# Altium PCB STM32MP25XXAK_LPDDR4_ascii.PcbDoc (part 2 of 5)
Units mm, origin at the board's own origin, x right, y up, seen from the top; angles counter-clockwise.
Board outline 120 x 79.6 mm, 4 copper layers (Top Layer, Signal Layer 1, Signal Layer 2, Bottom Layer), stack 1.614 mm thick; 190 components, 143 nets, 1208 pads, 757 vias.
Unrouted connection lines stored in the file: 3.
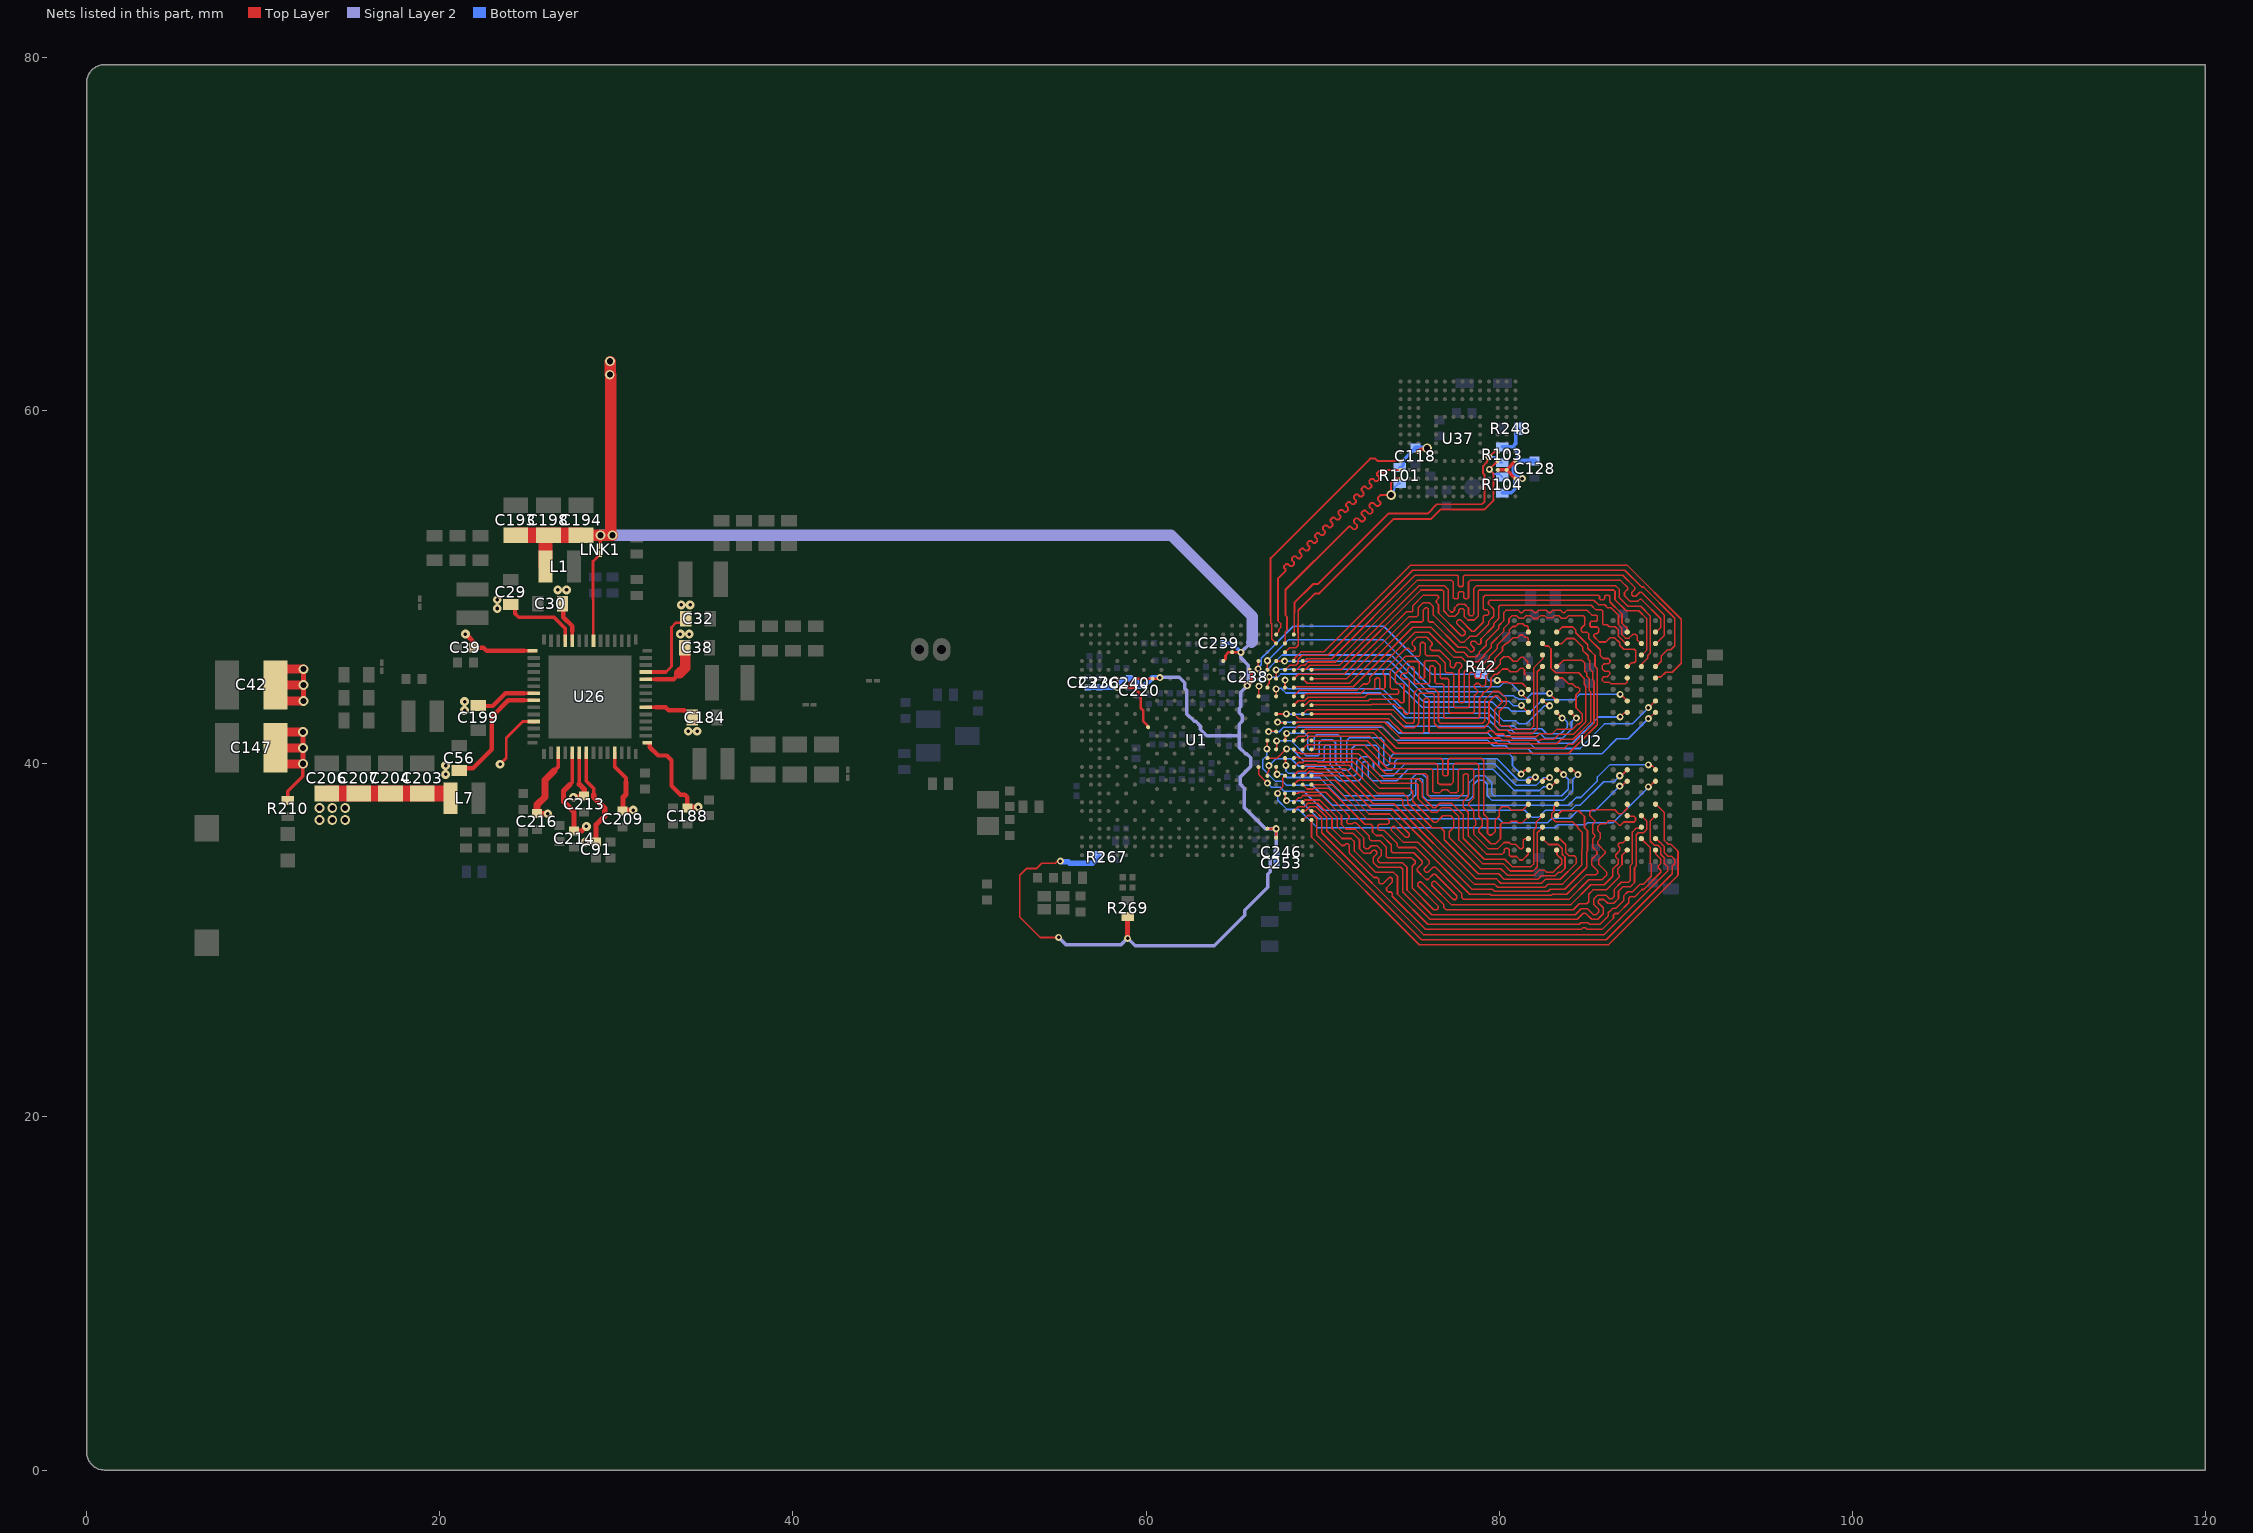
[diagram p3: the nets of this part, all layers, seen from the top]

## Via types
v1: diameter 0.55, hole 0.35, Top Layer to Bottom Layer, 277 vias
v2: diameter 0.4, hole 0.2, Top Layer to Bottom Layer, tented both sides, 229 vias
v3: diameter 0.5, hole 0.2, Top Layer to Bottom Layer, 146 vias
v4: diameter 0.4, hole 0.2, Top Layer to Bottom Layer, 105 vias

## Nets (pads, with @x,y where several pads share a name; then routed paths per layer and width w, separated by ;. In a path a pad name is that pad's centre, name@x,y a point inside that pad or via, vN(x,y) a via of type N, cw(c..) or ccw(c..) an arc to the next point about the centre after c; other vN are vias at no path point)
1V8: C118.2 C128.2 C193.2 C194.2 C198.2 C220.2 C236.2 C237.2 C238.2 C239.2 C240.2 C246.2 C253.2 L1.2 LNK1.2 R101.2 R103.2 R104.2 R248.2 R267.2 R269.1 U1.1E1 U1.AD22 U1.AE23 U1.D18 U1.E17 U1.F20 U1.G5 U1.G7 U1.G9 U1.G19 U1.H6 U37.C6 U37.M4 U37.N4 U37.P3 U37.P5 | length 137.4
  Top Layer w0.1: v2(55.049,30.165) 54.012,30.165 52.854,31.323 52.854,33.688 53.244,34.078 53.813,34.078 54.103,34.368 54.86,34.368 54.967,34.474 55.127,34.474 v2(55.146,34.494)
  Top Layer w0.15: U1.G5@58.375,44.825 v2(58.375,44.325) U1.H6@58.875,44.325 ; U1.1E1@60.125,42.075 60.125,42.097 60.085,42.137 60.085,42.17 59.835,42.42 59.835,43.035 59.702,43.168 59.702,43.926 59.304,44.325 U1.H6@58.875,44.325 ; v2@60.792,44.887 v2(60.79,44.885) 60.73,44.825 U1.G9@60.375,44.825 U1.G7@59.375,44.825 U1.H6@58.875,44.325 ; U1.E17@64.375,45.825 64.375,45.828 64.5,45.953 64.5,46.139 64.683,46.322 U1.D18@64.872,46.322 ; U1.D18@64.853,46.325 U1.D18@64.875,46.325 65.372,46.325 v2(65.378,46.319) ; U1.G19@65.378,44.822 65.735,44.465 v2(65.735,44.426) 65.735,44.412 65.973,44.651 65.973,45.205 65.875,45.303 U1.F20@65.875,45.325 ; U1.AD22@66.875,36.325 v2(67.375,36.325) U1.AE23@67.375,35.825 ; U37.P3@80.925,56.155 v2(81.325,56.155)
  Top Layer w0.2: LNK1.2@29.1,52.348 v1(29.1,52.95) ; U37.C6@75.425,57.655 75.602,57.832 75.877,57.832 v1(75.925,57.88) ; U37.M4@79.925,56.655 U37.N4@80.425,56.655 ; U37.P3@80.925,56.155 U37.N4@80.425,56.655 ; U37.P5@80.925,57.155 U37.N4@80.425,56.655
  Top Layer w0.3: R269.1@58.956,31.358 58.956,30.117 v2(58.962,30.112)
  Top Layer w0.64: C194.2@28,52.95 v1(29.1,52.95) v1(29.78,52.95) 29.674,53.056 v1@29.674,62.004 ; v1@29.66,62.075 v1@29.66,62.782
  Top Layer w0.8: L1.2@25.995,51.175 25.995,52.9 26.045,52.95 C198.2@26.15,52.95
  Top Layer w0.9: C193.2@24.3,52.95 C198.2@26.045,52.95 ; C198.2@26.15,52.95 C194.2@28,52.95
  Signal Layer 2 w0.2: v2(55.049,30.165) 55.449,29.766 58.598,29.766 v2@58.944,30.112 ; v2(58.962,30.112) 59.386,29.688 63.861,29.688 65.603,31.43 65.603,31.711 66.9,33.008 66.9,33.754 67.041,33.895 67.041,34.559 67.375,34.893 v2(67.375,36.325) ; v2(60.79,44.885) 60.811,44.906 61.89,44.906 62.2,44.596 62.2,44.264 62.32,44.144 62.32,42.814 62.725,42.409 62.81,42.409 63.077,42.143 ; 63.075,42.156 63.077,42.155 63.077,42.143 ; 65.285,41.575 65.285,40.928 65.64,40.572 65.694,40.572 65.93,40.336 65.93,39.851 65.349,39.271 65.349,38.835 65.569,38.615 65.569,37.527 65.566,37.525 66.77,36.322 v2@67.372,36.322 ; v2@65.674,44.353 65.773,44.452 65.773,44.591 65.794,44.612 65.794,45.583 65.378,45.999 v2(65.378,46.319) 65.927,46.868 65.981,46.868 ; v2@65.734,44.411 65.375,44.053 65.375,43.231 65.284,43.14 65.284,42.894 65.44,42.738 65.44,42.406 65.285,42.251 65.285,41.593 63.445,41.593 63.077,41.961 63.077,42.143
  Signal Layer 2 w0.64: v1@29.1,52.955 v1@29.78,52.955 ; v1(29.78,52.95) 61.405,52.95 ; 61.411,52.956 66.023,48.344 66.023,46.91 65.981,46.868
  Bottom Layer w0.15: v2(67.375,36.325) 67.375,34.827 67.391,34.811
  Bottom Layer w0.2: C239.2@64.4,46.837 64.86,46.837 v2(65.378,46.319) ; v2@65.735,44.411 65.958,44.635 65.958,44.819 C238.2@66.033,44.894 ; R101.2@74.375,56.775 74.425,56.775 74.58,56.93 74.58,57.2 75.08,57.7 75.08,57.725 75.235,57.88 C118.2@75.26,57.88 ; R103.2@80.171,57.961 80.769,57.961 ; R104.2@80.175,55.355 80.69,55.355 80.885,55.55 80.885,55.998 81.061,56.174 ; 81.075,57.136 81.075,57.655 80.769,57.961 ; R248.2@81.107,58.98 80.952,58.825 80.952,58.144 80.769,57.961
  Bottom Layer w0.25: C253.2@67.391,34.385 67.391,34.811 C246.2@67.391,34.986
  Bottom Layer w0.3: v2(55.146,34.494) 55.165,34.474 55.236,34.474 55.259,34.452 55.612,34.452 55.689,34.375 56.975,34.375 57.123,34.523 57.218,34.523 57.323,34.628 R267.2@57.323,34.723 ; C237.2@56.696,44.325 C236.2@57.35,44.325 v2@58.386,44.325 ; v2(58.375,44.325) 58.394,44.344 58.394,44.53 58.689,44.825 59.025,44.825 C240.2@59.025,44.85 ; C240.2@58.984,44.85 59.125,44.85 59.15,44.825 59.19,44.825 59.3,44.715 59.399,44.715 59.54,44.574 59.54,44.475 C220.2@59.609,44.406 59.634,44.431 59.911,44.431 60.372,44.892 60.783,44.892 v2(60.79,44.885) ; C118.2@75.26,57.88 v1(75.925,57.88) ; v2(81.325,56.155) 81.306,56.174 81.061,56.174 80.867,56.368 80.867,56.928 81.075,57.136 81.306,57.136 81.325,57.155 C128.2@82.015,57.155
  other v1: 29.631,62.047 29.642,62.8
1V8_FB: LNK1.1 U26.35 | length 5.1
  Top Layer w0.15: U26.35@28.7,46.97 28.7,49.311 28.675,49.336 28.675,51.473 LNK1.1@29.1,51.898
3V3: C203.2 C204.2 C206.2 C207.2 C216.2 L7.2 U26.3 U26.53 | length 15.3
  Top Layer w0.15: v3(23.41,39.977) 23.762,40.329 23.762,41.465 24.697,42.4 U26.53@25.33,42.4 ; U26.53@25.12,42.369 25.419,42.369 U26.53@25.45,42.4
  Top Layer w0.21: 26.473,39.598 26.7,39.825 U26.3@26.7,40.63
  Top Layer w0.3: C216.2@25.475,37.175 C216.2@25.5,37.175 v3@26.085,37.175
  Top Layer w0.4: C216.2@25.5,37.175 25.514,37.189 25.514,37.685 25.96,38.131 25.96,39.085 26.473,39.598
  Top Layer w0.9: C206.2@13.587,38.323 C203.2@19,38.323 20.362,38.323 L7.2@20.387,38.298
  other v1: 13.187,36.823 13.912,36.823 14.637,36.823 13.187,37.498 13.912,37.498 14.637,37.498
  other v3: 26.11,37.175
5V_HDMI: C91.1 U26.7 | length 6.1
  Top Layer w0.21: U26.7@28.3,40.63 28.3,39.025 28.715,38.61 28.715,38.253
  Top Layer w0.3: v3(28.24,35.58) C91.1@28.85,35.58 ; 28.715,38.253 28.715,38.118 29.335,37.498 29.335,37.035 28.85,36.55 C91.1@28.85,35.73
5V_STLK: C29.2 C30.2 C32.2 C38.2 C39.2 C42.1 C56.2 C147.1 C184.2 C188.2 C199.2 C209.2 C213.2 R210.1 U26.6 U26.11 U26.15 U26.20 U26.24 U26.25 U26.38 U26.39 U26.43 U26.49 U26.50 | length 61
  Top Layer w0.15: 32.8,45.2 33.125,45.525 33.125,47.731 33.388,47.994 33.819,47.994 C32.2@33.925,48.1
  Top Layer w0.2: R210.1@11.386,37.915 11.386,38.449 12.244,39.307 v1@12.244,39.994
  Top Layer w0.21: C29.2@24.025,49.05 24.262,48.813 24.262,48.513 24.475,48.3 26.464,48.3 27.1,47.664 U26.39@27.1,46.97 ; 24.775,43.6 U26.50@25.33,43.6 ; 24.775,44 U26.49@25.33,44 ; 24.775,46.4 U26.43@25.33,46.4 ; U26.38@27.5,46.97 27.5,47.525 ; 27.9,38.85 U26.6@27.9,40.63 ; U26.11@29.9,40.63 29.9,39.843 30.54,39.203 30.54,38.975 ; U26.15@31.67,41.2 U26.15@31.745,41.2 U26.15@31.785,41.2 ; U26.20@31.67,43.2 32.225,43.2 ; U26.24@31.67,44.8 32.207,44.8 ; U26.25@31.67,45.2 32.8,45.2
  Top Layer w0.25: C56.2@21.1,39.75 21.875,39.75 22.95,40.825 22.95,42.669 23.881,43.6 24.775,43.6 ; 21.695,47.125 21.699,47.125 21.845,46.979 21.845,46.685 C39.2@21.955,46.575 ; C39.2@22.005,46.575 22.475,46.575 22.65,46.4 24.775,46.4 ; C199.2@22.175,43.275 22.991,43.275 23.716,44 24.775,44 ; C30.2@26.925,49.075 26.994,49.006 26.994,48.308 27.5,47.802 27.5,47.525 ; 31.895,41.095 31.895,40.947 32.371,40.472 32.853,40.472 33.125,40.2 33.125,38.759 33.634,38.25 33.879,38.25 34.025,38.104 C188.2@34.025,37.55 ; 32.207,44.8 33.25,44.8 33.575,45.125 ; 32.225,43.2 32.788,43.2 32.963,43.025 33.847,43.025 33.972,42.9 34.05,42.9 34.247,42.703 C184.2@34.247,42.625
  Top Layer w0.3: v1@12.25,40 12.25,40.902 12.25,40.906 v1@12.25,41.8 ; v1@12.275,43.563 12.275,44.463 v1@12.275,45.363 ; v3@21.444,47.376 21.695,47.125 ; v3(27.565,38.11) 28.175,38.11 28.174,38.111 28.174,38.576 27.9,38.85 ; C209.2@30.35,37.38 C209.2@30.375,37.38 ; 30.54,38.975 30.54,38.269 30.375,38.104 C209.2@30.375,37.38 ; v3(30.96,37.38) C209.2@30.375,37.38 ; C188.2@34.025,37.55 v3(34.635,37.55)
  Top Layer w0.5: C147.1@10.686,39.994 12.244,39.994 v1@12.269,39.994 ; C147.1@10.686,40.906 12.25,40.906 v1@12.269,40.906 ; C147.1@10.686,41.806 v1@12.269,41.806 ; C42.1@10.686,43.557 v1@12.269,43.557 ; C42.1@10.686,44.468 v1@12.269,44.468 ; C42.1@10.686,45.368 v1@12.269,45.368
  Top Layer w0.6: 33.575,45.125 33.9,45.45 C38.2@33.9,46.175
  other v1: 12.251,40.002 12.251,40.902 12.251,41.802 12.276,43.565 12.276,44.465 12.276,45.365
  other v3: 20.325,39.4 20.325,39.9 34.075,41.85 34.575,41.85 21.4,43.025 21.4,43.525 21.45,47.348 33.625,47.35 34.125,47.35 23.25,48.8 33.675,49 34.175,49 23.25,49.3 26.675,49.85 27.175,49.85
5V_VCONN: C214.1 U26.5 | length 5.7
  Top Layer w0.21: 27.378,38.827 27.5,38.95 U26.5@27.5,40.63
  Top Layer w0.3: 27.378,38.827 27.01,38.46 27.01,37.865 27.6,37.275 C214.1@27.6,36.2 28.04,36.2 v3(28.3,36.46)
DDR_CA0_A: U1.V24 U2.H2 | length 24.6
  Top Layer w0.09: v2@67.471,38.421 67.471,38.432 67.735,38.695 67.735,39.185 U1.V24@67.875,39.325 ; v4(88.46,38.69) 88.497,38.69 88.814,39.007 U2.H2@88.873,39.007
  Bottom Layer w0.09: v2@67.463,38.318 67.463,37.935 67.983,37.415 68.659,37.415 69.683,36.39 83.176,36.39 83.326,36.54 84.88,36.54 85.007,36.667 86.447,36.667 v4@88.461,38.681
  other v2: 67.46,38.325
DDR_CA0_B: U1.M24 U2.R2 | length 23.5
  Top Layer w0.09: v2@67.46,42.35 67.484,42.326 U1.M24@67.875,42.325 ; v4@88.472,43.19 88.826,43.544 U2.R2@88.859,43.544
  Bottom Layer w0.09: v2(67.46,42.365) 73.699,42.365 ; 73.7,42.36 74.314,41.746 79.358,41.746 79.791,41.313 80.496,41.313 80.654,41.155 81.746,41.155 82.031,40.87 84.581,40.87 85.973,42.262 87.538,42.262 v4@88.461,43.185
  other v4: 88.46,43.19
DDR_CA1_A: U1.P22 U2.J2 | length 25.9
  Top Layer w0.09: v2@66.875,40.9 U1.P22@66.875,41.325 ; v4(88.46,39.94) 88.518,39.881 88.689,39.881 88.86,39.71 U2.J2@88.86,39.665
  Bottom Layer w0.09: v2@66.851,40.845 66.851,40.48 66.622,40.251 66.622,40.045 66.62,40.043 66.62,39.757 66.622,39.755 66.622,39.721 67.339,39.005 67.74,39.005 67.954,38.791 69.421,38.791 70.552,37.66 83.935,37.66 84.371,38.096 84.618,38.096 85.572,39.05 85.572,39.255 86.257,39.94 v4(88.46,39.94)
  other v2: 66.85,40.85
DDR_CA1_B: U1.N23 U2.P2 | length 24
  Top Layer w0.09: v2@66.946,41.838 67.362,41.838 U1.N23@67.375,41.825 ; v4(88.46,42.565) 88.483,42.565 88.833,42.915 U2.P2@88.86,42.915
  Bottom Layer w0.09: v2(66.95,41.825) 67.542,41.825 67.792,42.075 73.404,42.075 74.153,41.326 79.367,41.326 79.669,41.023 80.374,41.023 80.533,40.865 81.624,40.865 81.909,40.58 85.826,40.58 86.671,41.425 87.315,41.425 88.45,42.56 v4@88.461,42.56
DDR_CA2_A: U1.V22 U2.H9 | length 20.3
  Top Layer w0.09: U1.V22@66.877,39.334 66.877,39.497 66.947,39.567 66.947,39.847 v2@66.95,39.85 ; v4@82.859,38.719 82.913,38.774 83.019,38.774 U2.H9@83.26,39.015
  Bottom Layer w0.09: v2@66.966,39.895 67.358,40.287 68.23,40.287 68.647,39.869 70.104,39.869 70.926,39.046 72.053,39.046 72.239,39.232 72.239,40.017 72.339,40.117 72.501,40.117 72.595,40.024 72.595,39.281 72.83,39.046 74.2,39.046 74.859,39.705 79.637,39.705 80.852,38.49 82.293,38.49 82.511,38.708 v4@82.86,38.708
  other v2: 66.965,39.9
  other v4: 82.86,38.715
DDR_CA2_B: U1.J21 U2.R9 | length 19.8
  Top Layer w0.09: U1.J21@66.375,43.825 66.387,43.837 v2@66.387,44.388 ; v4(82.86,43.99) 82.86,43.977 83.26,43.577 U2.R9@83.26,43.565
  Bottom Layer w0.09: v2(66.4,44.4) 66.4,44.478 66.494,44.572 66.494,44.951 67.71,46.166 73.892,46.166 75.974,44.084 79.99,44.084 80.217,43.857 80.817,43.857 80.918,43.756 81.021,43.756 81.117,43.66 81.519,43.66 81.846,43.987 v4@82.858,43.987
DDR_CA3_A: U1.T22 U2.H10 | length 21.6
  Top Layer w0.09: U1.T22@66.875,40.325 67.433,40.325 v2(67.961,40.853) ; U2.H10@82.467,39.008 82.625,39.166 82.801,39.166 v4(82.86,39.225)
  Bottom Layer w0.09: v2@67.964,40.849 68.253,40.849 68.943,40.159 70.015,40.159 70.104,40.248 70.104,40.975 70.195,41.066 70.356,41.066 70.443,40.978 70.443,39.939 71.046,39.336 71.816,39.336 71.949,39.469 71.949,40.137 72.219,40.407 72.621,40.407 72.885,40.144 72.885,39.706 73.255,39.336 74.013,39.336 74.671,39.995 79.757,39.995 80.972,38.78 82.094,38.78 82.534,39.22 v4@82.861,39.22
DDR_CA3_B: U1.H22 U2.R10 | length 18.7
  Top Layer w0.09: U1.H22@66.875,44.325 66.9,44.35 66.9,44.496 66.975,44.571 66.975,44.918 v2(66.971,44.921) ; U2.R10@82.46,43.565 82.514,43.565 82.789,43.29 v4(82.86,43.29)
  Bottom Layer w0.09: v2@66.972,44.916 67.471,44.916 67.646,45.091 73.736,45.091 75.628,43.2 79.488,43.2 80.255,42.433 80.96,42.433 81.118,42.275 81.559,42.275 82.569,43.285 v4@82.861,43.285
DDR_CA4_A: U1.R23 U2.H11 | length 21.6
  Top Layer w0.09: U1.R23@67.375,40.825 67.4,40.85 v2(67.4,41.3) ; U2.H11@81.66,39.015 81.714,39.015 81.882,39.183 82.003,39.183 v4(82.06,39.24)
  Bottom Layer w0.09: v2(67.4,41.3) 68.236,41.3 69.072,40.465 69.736,40.465 69.814,40.543 69.814,41.209 69.962,41.356 70.569,41.356 70.733,41.192 70.733,40.059 71.166,39.626 71.466,39.626 71.659,39.819 71.659,40.858 71.849,41.048 73.031,41.048 73.175,40.904 73.175,39.826 73.375,39.626 73.892,39.626 74.093,39.826 74.093,40.136 74.241,40.285 79.877,40.285 81.092,39.07 81.517,39.07 81.686,39.239 v4@82.057,39.239
DDR_CA4_B: U1.F22 U2.R11 | length 17.4
  Top Layer w0.09: U1.F22@66.875,45.325 v2(66.875,45.841) ; v4@81.26,43.99 81.66,43.59 U2.R11@81.66,43.565
  Bottom Layer w0.09: v2@66.876,45.836 68.06,47.02 73.448,47.02 76.094,44.374 80.027,44.374 ; 80.044,44.379 80.249,44.584 80.665,44.584 v4@81.259,43.99
  other v4: 81.26,44.005
DDR_CA5_A: U1.P24 U2.J11 | length 21.1
  Top Layer w0.09: U1.P24@67.875,41.325 67.902,41.352 67.902,41.702 v2@67.95,41.75 ; v4@81.235,39.415 81.461,39.641 81.636,39.641 U2.J11@81.66,39.665
  Bottom Layer w0.09: v2@67.971,41.725 69.016,41.725 69.155,41.586 69.155,40.888 69.257,40.786 69.444,40.786 69.524,40.867 69.524,41.508 69.662,41.646 70.873,41.646 71.023,41.496 71.023,40.18 71.125,40.078 71.257,40.078 71.369,40.19 71.369,41.327 71.513,41.471 73.311,41.471 73.465,41.317 73.465,40.008 73.556,39.916 73.712,39.916 73.803,40.007 73.803,40.351 74.032,40.58 80.558,40.58 80.76,40.378 80.76,40.364 80.761,40.363 80.761,39.9 v4@81.251,39.41
  other v2: 67.97,41.73
  other v4: 81.25,39.415
DDR_CA5_B: U1.E23 U2.P11 | length 15.5
  Top Layer w0.09: U1.E23@67.375,45.825 67.377,45.823 67.852,45.823 v2(67.855,45.82) ; v4@81.268,43.3 81.652,42.915 U2.P11@81.66,42.915
  Bottom Layer w0.09: v2@67.856,45.815 73.833,45.815 75.854,43.794 79.829,43.794 80.085,43.538 80.573,43.538 80.822,43.289 81.24,43.289 v4@81.261,43.31
  other v4: 81.26,43.315
DDR_CKE0_A: U1.U21 U2.J4 | length 23.3
  Top Layer w0.09: U1.U21@66.376,39.833 66.376,39.409 v2(66.875,38.91) ; v4@86.979,39.384 U2.J4@87.26,39.665
  Bottom Layer w0.09: v2@66.876,38.905 67.111,38.67 67.603,38.67 67.818,38.455 68.939,38.455 70.024,37.37 81.458,37.37 81.863,36.965 82.229,36.965 82.629,37.365 84.05,37.365 84.329,37.644 84.576,37.644 85.922,38.99 86.515,38.99 v4@86.836,39.311
  other v4: 86.835,39.325
DDR_CKE0_B: U1.L23 U2.P4 | length 21.3
  Top Layer w0.09: U1.L23@67.375,42.825 67.816,42.826 67.88,42.889 v2@67.965,42.889 ; v4(86.86,42.665) 87.079,42.884 87.229,42.884 U2.P4@87.26,42.915
  Bottom Layer w0.09: v2@67.951,42.82 73.855,42.82 74.555,42.12 79.395,42.12 79.911,41.603 80.616,41.603 80.774,41.445 82.02,41.445 82.305,41.16 84.141,41.16 85.634,42.654 v4@86.855,42.654
  other v2: 67.95,42.825
DDR_CLK_A_N: U1.T24 U2.J9 | length 22.6
  Top Layer w0.09: U1.T24@67.876,40.333 67.901,40.308 67.901,39.933 v2@67.926,39.908 ; U2.J9@83.26,39.665 83.3,39.625 83.428,39.625 v4@83.659,39.394
  Bottom Layer w0.09: v2@67.929,39.902 67.929,39.595 68.048,39.476 69.936,39.476 71.211,38.2 74.886,38.2 75.034,38.348 75.034,39.159 75.29,39.415 75.683,39.415 75.925,39.172 75.925,38.286 76.011,38.2 78.213,38.2 78.291,38.277 78.291,38.915 78.692,39.316 79.204,39.316 79.578,38.941 79.578,38.301 79.68,38.2 83.553,38.2 83.915,38.561 83.915,39.135 v4(83.66,39.39)
  other v2: 67.925,39.91
DDR_CLK_A_P: U1.U23 U2.J8 | length 23.2
  Top Layer w0.09: U1.U23@67.375,39.825 67.375,39.46 v2(67.425,39.41) ; U2.J8@84.06,39.665 84.1,39.625 84.217,39.625 84.448,39.394 v4@84.459,39.394
  Bottom Layer w0.09: v2@67.427,39.404 67.766,39.404 67.945,39.226 69.832,39.226 71.108,37.95 74.989,37.95 75.284,38.245 75.284,39.055 75.393,39.165 75.579,39.165 75.675,39.069 75.675,38.182 75.908,37.95 78.317,37.95 78.541,38.174 78.541,38.811 78.795,39.066 79.1,39.066 79.328,38.838 79.328,38.198 79.576,37.95 83.657,37.95 84.165,38.458 84.165,39.096 v4(84.46,39.39)
DDR_CLK_B_N: U1.H24 U2.P9 | length 19.1
  Top Layer w0.09: U1.H24@67.875,44.325 v2(67.875,44.74) ; U2.P9@83.26,42.915 83.574,42.601 v4(83.574,42.59)
  Bottom Layer w0.09: v2(67.875,44.74) 67.851,44.716 67.851,44.441 68.027,44.265 73.389,44.265 74.785,42.869 79.409,42.869 80.135,42.143 80.839,42.143 80.998,41.985 82.422,41.985 82.707,41.7 83.49,41.7 83.85,42.06 83.85,42.383 83.649,42.584 v4@83.575,42.584
DDR_CLK_B_P: U1.J23 U2.P8 | length 19.8
  Top Layer w0.09: U1.J23@67.375,43.825 v2(67.375,44.24) ; U2.P8@84.06,42.915 84.06,42.909 v4@84.374,42.595
  Bottom Layer w0.09: v2@67.381,44.24 67.422,44.281 67.658,44.281 67.924,44.015 73.285,44.015 74.681,42.619 79.305,42.619 80.031,41.893 80.736,41.893 80.894,41.735 82.319,41.735 82.604,41.45 83.593,41.45 84.1,41.957 84.1,42.383 84.306,42.59 v4(84.374,42.59)
DDR_CS0_A: U1.Y24 U2.H4 | length 21.2
  Top Layer w0.09: U1.Y24@67.876,38.333 67.891,38.319 67.891,37.977 v2@67.967,37.901 ; v4(86.835,38.74) 86.893,38.799 87.002,38.799 87.217,39.015 U2.H4@87.26,39.015
  Bottom Layer w0.09: v2@67.971,37.915 68.747,37.915 69.769,36.893 79.992,36.893 80.209,36.675 82.756,36.675 83.005,36.924 84.02,36.924 84.45,37.354 85.449,37.354 v4(86.835,38.74)
  other v2: 67.97,37.92
DDR_CS0_B: U1.G23 U2.R4 | length 22
  Top Layer w0.09: U1.G23@67.375,44.825 v2(67.375,45.325) ; v4(86.86,43.94) 86.885,43.94 U2.R4@87.26,43.565
  Bottom Layer w0.09: v2@67.374,45.321 67.377,45.321 67.426,45.37 73.868,45.37 75.734,43.504 79.608,43.504 79.934,43.179 80.507,43.179 80.716,42.969 81.116,42.969 ; v4@86.861,43.935 84.557,43.935 84.257,43.635 82.461,43.635 81.791,42.965 81.786,42.97 81.117,42.97 ; 81.116,42.969 81.117,42.97
DDR_DQ0_A: U1.AB26 U2.B2 | length 28.6
  Top Layer w0.09: U1.AB26@68.875,37.325 68.901,37.351 69.047,37.351 69.271,37.575 69.643,37.575 70.245,36.973 70.245,36.216 71.087,35.374 71.222,35.374 71.329,35.481 71.433,35.481 71.516,35.398 71.516,34.945 72.9,33.561 73.102,33.561 73.182,33.482 73.182,33.279 73.261,33.2 73.413,33.2 73.775,33.561 73.886,33.561 73.956,33.492 73.956,33.304 73.623,32.971 73.623,32.838 73.718,32.743 73.877,32.743 73.956,32.664 73.956,32.505 75.841,30.62 84.663,30.62 84.748,30.705 84.917,30.705 85.001,30.62 85.834,30.62 86.48,31.266 86.48,31.447 86.554,31.521 86.735,31.521 87.343,32.129 87.343,32.392 87.415,32.464 87.678,32.464 88.095,32.881 88.187,32.881 89.159,33.853 89.159,33.975 89.016,34.117 89.016,34.218 89.159,34.361 89.159,34.609 88.878,34.89 88.878,35.075 U2.B2@88.859,35.094
DDR_DQ0_B: U1.F25 U2.AA2 | length 27.9
  Top Layer w0.09: U1.F25@68.375,45.325 68.389,45.339 68.535,45.339 68.771,45.575 68.979,45.575 68.983,45.579 68.992,45.579 69.182,45.769 70.734,45.769 75.355,50.39 77.311,50.39 77.399,50.301 77.399,49.414 77.47,49.344 77.625,49.344 77.696,49.415 77.696,49.699 77.751,49.754 77.943,49.754 77.996,49.701 77.996,49.416 78.069,49.344 78.198,49.344 78.269,49.414 78.269,50.298 78.361,50.39 86.882,50.39 87.285,49.987 87.285,49.888 87.106,49.71 87.106,49.524 87.419,49.21 87.854,49.21 87.957,49.313 88.065,49.313 89.154,48.224 89.154,47.723 88.875,47.444 U2.AA2@88.859,47.444
DDR_DQ1_A: U1.AC26 U2.C2 | length 28.7
  Top Layer w0.09: U1.AC26@68.877,36.829 68.897,36.829 69.143,37.075 69.479,37.075 69.665,36.889 69.665,35.976 75.601,30.04 86.074,30.04 89.813,33.779 89.813,34.215 89.945,34.347 89.945,34.585 89.761,34.769 89.567,34.769 89.364,34.972 89.364,35.306 88.905,35.765 U2.C2@88.86,35.765
DDR_DQ1_B: U1.E26 U2.Y2 | length 27.1
  Top Layer w0.09: U1.E26@68.877,45.829 68.9,45.852 68.996,45.852 69.103,45.959 70.514,45.959 75.235,50.68 77.637,50.68 77.689,50.627 77.689,50.097 77.742,50.044 77.926,50.044 77.979,50.097 77.979,50.614 78.045,50.68 87.002,50.68 87.695,49.987 87.695,49.889 87.518,49.712 87.518,49.577 87.596,49.5 87.734,49.5 87.96,49.726 88.062,49.726 89.364,48.424 89.364,47.29 88.868,46.794 U2.Y2@88.859,46.794
DDR_DQ2_A: U1.AB27 U2.E2 | length 28.9
  Top Layer w0.09: U1.AB27@69.375,37.325 69.571,37.325 69.955,36.941 69.955,36.096 75.721,30.33 85.954,30.33 89.564,33.94 89.564,34.158 89.349,34.373 89.349,34.687 89.154,34.882 89.154,35.237 88.991,35.4 88.786,35.4 88.564,35.622 88.564,36.769 U2.E2@88.86,37.065
DDR_DQ2_B: U1.F24 U2.V2 | length 29
  Top Layer w0.09: U1.F24@67.875,45.325 68.125,45.575 68.479,45.575 68.625,45.721 68.625,45.929 68.845,46.149 70.294,46.149 75.115,50.97 87.122,50.97 88.076,50.016 88.182,50.016 89.945,48.253 89.945,46.697 89.717,46.469 89.542,46.469 89.187,46.114 89.187,45.804 88.877,45.494 U2.V2@88.859,45.494
DDR_DQ3_A: U1.AC27 U2.F2 | length 30.5
  Top Layer w0.09: U1.AC27@69.375,36.825 69.375,35.856 75.481,29.75 86.194,29.75 90.135,33.691 90.135,35.043 89.738,35.44 89.582,35.44 89.364,35.658 89.364,37.233 88.882,37.715 U2.F2@88.86,37.715
DDR_DQ3_B: U1.E25 U2.U2 | length 29.8
  Top Layer w0.09: U1.E25@68.375,45.825 68.402,45.852 68.402,45.96 68.781,46.339 70.074,46.339 74.995,51.26 87.242,51.26 90.317,48.185 90.317,45.697 89.814,45.194 89.434,45.194 89.159,44.919 88.934,44.919 U2.U2@88.859,44.844
DDR_DQ4_A: U1.W25 U2.F4 | length 29.9
  Top Layer w0.09: U1.W25@68.374,38.826 68.623,39.075 70.717,39.075 72.632,37.16 73.793,37.16 74.916,36.037 74.916,35.923 74.835,35.842 74.699,35.842 74.088,36.454 73.97,36.454 73.882,36.366 73.882,36.249 74.58,35.551 75.401,35.551 78.342,32.61 79.496,32.61 79.557,32.55 82.962,32.55 83.022,32.61 83.838,32.61 84.956,33.728 85.488,33.728 85.578,33.818 85.578,33.949 85.251,34.276 85.251,34.598 85.548,34.895 85.548,35.03 85.309,35.269 85.309,35.744 85.409,35.844 85.409,35.988 85.309,36.088 85.309,36.579 85.409,36.679 85.409,36.791 85.129,37.071 85.129,37.261 85.267,37.399 86.546,37.399 86.783,37.162 86.93,37.162 87.255,37.487 U2.F4@87.255,37.71
DDR_DQ4_B: U1.J25 U2.U4 | length 28.2
  Top Layer w0.09: U1.J25@68.375,43.825 68.375,43.842 68.71,44.177 71.957,44.177 72.305,44.525 72.536,44.525 72.664,44.653 72.664,44.884 75.234,47.454 76.021,47.454 77.447,46.028 77.89,46.028 78.138,45.78 78.821,45.78 79.158,46.117 79.158,46.196 79.557,46.596 79.557,46.81 80.273,47.527 ; 80.274,47.527 80.274,47.693 80.564,47.982 80.564,48.222 80.742,48.4 80.978,48.4 81.135,48.243 81.385,48.243 81.542,48.4 81.778,48.4 81.946,48.233 82.174,48.233 82.342,48.4 82.578,48.4 82.713,48.266 83.007,48.266 83.142,48.4 83.378,48.4 83.524,48.254 83.796,48.254 83.942,48.4 84.767,48.4 84.86,48.307 84.86,47.879 84.656,47.674 84.656,47.525 84.737,47.445 85.004,47.445 85.076,47.373 85.076,47.105 85.724,46.457 85.724,46.142 85.897,45.969 86.184,45.969 86.281,45.871 86.281,45.761 86.197,45.677 85.962,45.677 85.854,45.569 85.854,45.362 85.968,45.247 86.183,45.247 86.258,45.172 86.258,45.067 86.121,44.929 85.936,44.929 85.854,44.847 85.854,44.724 85.948,44.63 86.237,44.63 86.339,44.528 87.147,44.528 87.261,44.641 U2.U4@87.26,44.865
DDR_DQ5_A: U1.W27 U2.E4 | length 29.1
  Top Layer w0.09: U1.W27@69.377,38.829 69.391,38.815 70.567,38.815 72.512,36.87 73.673,36.87 73.773,36.77 73.773,36.667 73.683,36.577 73.207,36.577 73.121,36.491 73.121,36.304 73.196,36.229 73.492,36.229 74.22,35.501 74.222,35.5 74.222,35.345 74.305,35.261 75.28,35.261 75.892,34.65 ; 75.892,34.65 76.055,34.488 76.055,34.351 75.765,34.061 75.765,33.956 75.864,33.857 75.972,33.857 76.263,34.148 76.394,34.148 77.891,32.651 77.891,32.428 77.999,32.32 83.959,32.32 85.076,33.438 85.83,33.438 86.109,33.718 86.109,33.842 85.654,34.297 85.654,34.591 86.003,34.94 86.003,35.041 85.599,35.445 85.599,35.624 85.722,35.747 85.722,36.085 85.599,36.208 85.599,36.457 85.759,36.617 86.055,36.617 86.218,36.78 86.544,36.78 86.791,36.533 86.893,36.533 87.065,36.705 87.645,36.705 87.728,36.787 87.728,36.944 87.646,37.025 87.3,37.025 U2.E4@87.26,37.065
DDR_DQ5_B: U1.H25 U2.V4 | length 27.7
  Top Layer w0.09: U1.H25@68.375,44.325 68.417,44.367 71.737,44.367 75.114,47.744 76.141,47.744 77.568,46.318 78.01,46.318 78.258,46.07 78.701,46.07 78.868,46.237 78.868,46.316 79.267,46.716 79.267,46.954 79.983,47.67 79.984,47.828 80.274,48.117 80.274,48.577 80.387,48.69 81.098,48.69 81.223,48.565 81.297,48.565 81.422,48.69 81.898,48.69 82.022,48.566 82.097,48.566 82.221,48.69 82.698,48.69 82.823,48.565 82.897,48.565 83.022,48.69 83.498,48.69 83.583,48.605 83.623,48.565 83.697,48.565 83.822,48.69 85,48.69 85.261,48.429 85.5,48.429 85.559,48.37 85.559,48.135 85.506,48.082 85.228,48.082 85.15,48.004 85.15,47.804 85.203,47.751 85.561,47.751 85.645,47.667 85.645,47.478 85.537,47.37 85.437,47.37 85.366,47.3 85.366,47.225 85.688,46.904 86.046,46.904 86.274,47.132 86.558,47.132 86.837,46.853 86.837,46.715 87.061,46.491 87.654,46.491 87.742,46.404 87.742,45.81 87.662,45.73 87.506,45.73 87.27,45.494 U2.V4@87.259,45.494
DDR_DQ6_A: U1.W26 U2.C4 | length 29.1
  Top Layer w0.09: U1.W26@68.875,38.825 69.125,38.575 69.479,38.575 69.529,38.625 70.347,38.625 72.392,36.58 72.738,36.58 72.831,36.487 72.831,36.141 73.032,35.939 73.372,35.939 73.897,35.415 73.897,35.054 73.979,34.971 75.16,34.971 75.652,34.479 75.652,34.359 75.366,34.072 75.366,33.946 75.863,33.448 75.973,33.448 76.271,33.746 76.386,33.746 77.601,32.531 77.601,32.389 77.532,32.319 77.402,32.319 76.38,33.341 76.276,33.341 76.18,33.245 76.18,33.13 77.28,32.03 84.079,32.03 85.196,33.148 85.952,33.148 86.441,33.637 ; U2.C4@87.26,35.765 87.037,35.542 86.835,35.542 86.745,35.452 86.745,35.345 86.836,35.254 86.836,35.088 86.605,34.857 86.605,34.723 86.747,34.581 86.747,34.448 86.745,34.446 86.745,34.347 86.44,34.042 86.44,33.638 ; 86.44,33.638 86.441,33.637
DDR_DQ6_B: U1.G26 U2.Y4 | length 25.9
  Top Layer w0.09: U1.G26@68.877,44.829 69.133,44.573 71.533,44.573 74.994,48.034 75.629,48.034 75.7,48.106 75.7,48.718 75.828,48.846 75.923,48.846 75.989,48.779 75.989,48.104 76.059,48.034 76.261,48.034 77.687,46.608 77.972,46.608 78.131,46.608 78.378,46.36 78.502,46.36 78.596,46.455 78.596,46.553 78.391,46.759 78.391,46.862 78.466,46.938 78.634,46.938 78.807,46.765 78.906,46.765 78.977,46.836 78.977,47.074 79.694,47.792 79.694,47.948 79.984,48.238 79.984,48.899 80.065,48.98 85.224,48.98 85.485,48.719 85.811,48.719 85.864,48.666 85.864,47.944 85.932,47.876 86.13,47.876 86.247,47.759 86.577,47.759 86.754,47.582 86.754,47.248 87.208,46.794 U2.Y4@87.259,46.794
DDR_DQ7_A: U1.Y25 U2.B4 | length 29.9
  Top Layer w0.09: U1.Y25@68.375,38.325 68.62,38.325 68.682,38.387 70.174,38.387 71.498,37.064 71.498,36.927 71.365,36.794 71.365,36.68 71.444,36.601 71.698,36.601 71.771,36.674 71.888,36.674 72.636,35.926 72.636,35.768 72.76,35.644 73.257,35.644 73.606,35.296 73.606,34.757 73.682,34.681 75.04,34.681 75.246,34.476 75.246,34.362 75.076,34.192 75.076,32.969 76.305,31.74 76.487,31.74 76.565,31.818 76.565,31.925 75.391,33.098 75.391,33.218 75.481,33.307 75.593,33.307 76.865,32.035 76.865,31.863 76.988,31.74 84.199,31.74 84.54,32.082 84.963,32.082 85.073,32.191 85.073,32.614 85.316,32.858 86.072,32.858 86.807,33.593 86.807,33.701 86.731,33.777 86.731,34.064 86.964,34.297 86.964,34.819 U2.B4@87.26,35.115
DDR_DQ7_B: U1.G25 U2.AA4 | length 28.3
  Top Layer w0.09: U1.G25@68.374,44.826 68.623,45.075 71.214,45.075 74.754,48.614 75.062,48.614 75.12,48.673 75.12,48.958 75.722,49.56 76.504,49.56 76.569,49.494 76.569,49.369 76.455,49.254 76.455,49.134 76.569,49.02 76.569,48.547 77.854,47.262 77.97,47.262 78.08,47.372 78.08,47.483 77.609,47.954 77.609,48.064 77.706,48.161 77.814,48.161 78.456,47.518 78.6,47.518 79.099,48.016 79.099,48.341 79.169,48.412 79.329,48.412 79.403,48.485 79.403,48.642 79.316,48.729 79.17,48.729 79.099,48.8 79.099,49.443 79.216,49.56 85.622,49.56 ; 85.623,49.56 85.69,49.493 85.69,49.367 85.758,49.299 85.914,49.299 85.98,49.365 85.98,49.497 86.043,49.56 86.21,49.56 86.276,49.494 86.276,49.18 86.964,48.492 86.964,47.972 87.259,47.677 U2.AA4@87.259,47.444
DDR_DQ8_A: U1.R27 U2.B11 | length 20.4
  Top Layer w0.09: U1.R27@69.378,40.828 72.189,40.828 73.576,39.44 75.832,39.44 75.945,39.327 75.945,38.257 76.14,38.062 77.697,38.062 77.975,38.34 77.975,39.352 78.063,39.44 78.177,39.44 78.265,39.352 78.265,38.163 77.976,37.874 77.976,37.541 78.258,37.259 78.258,37.23 78.265,37.223 78.265,35.912 79.028,35.149 79.287,34.89 80.187,34.89 80.285,34.988 80.285,35.141 80.36,35.215 80.498,35.215 80.575,35.138 80.575,34.826 80.65,34.751 80.987,34.751 81.183,34.555 81.332,34.555 81.659,34.882 U2.B11@81.66,35.115
DDR_DQ8_B: U1.J26 U2.AA11 | length 23.9
  Top Layer w0.09: U1.J26@68.875,43.825 68.879,43.829 68.915,43.829 69.065,43.979 72.169,43.979 72.425,44.235 72.874,44.235 72.954,44.314 72.954,44.764 73.065,44.875 73.172,44.875 73.243,44.804 73.243,44.315 73.324,44.235 73.454,44.235 73.536,44.316 73.536,44.977 73.449,45.063 73.449,45.259 74.749,46.559 74.863,46.559 75.035,46.387 75.157,46.387 75.235,46.465 75.235,46.605 75.074,46.767 75.074,46.884 75.354,47.164 75.901,47.164 76.198,46.867 76.198,46.72 76.106,46.628 76.106,46.499 76.182,46.423 76.642,46.423 77.239,45.827 77.239,45.535 77.328,45.446 77.425,45.446 77.529,45.55 77.529,45.662 77.605,45.738 77.77,45.738 77.886,45.622 77.886,45.497 77.73,45.342 77.73,43.53 77.8,43.46 77.952,43.46 78.02,43.528 78.02,45.22 78.29,45.49 78.658,45.49 78.748,45.399 78.851,45.399 79.448,45.997 79.448,46.076 79.903,46.531 ; 79.904,46.531 79.904,46.746 80.575,47.417 80.575,47.583 80.771,47.779 80.931,47.779 81.091,47.939 81.34,47.939 81.449,47.83 81.563,47.83 81.659,47.734 U2.AA11@81.66,47.465
DDR_DQ9_A: U1.R26 U2.C11 | length 21.2
  Top Layer w0.09: U1.R26@68.875,40.825 69.125,41.075 72.352,41.075 73.697,39.73 76.134,39.73 76.235,39.629 76.235,38.453 76.336,38.352 76.622,38.352 76.809,38.539 77.063,38.539 77.25,38.352 77.577,38.352 77.685,38.46 77.685,39.625 77.79,39.73 78.453,39.73 78.555,39.628 78.555,38.043 78.292,37.78 78.292,37.635 78.555,37.372 78.555,36.912 78.676,36.791 78.676,36.538 78.555,36.417 78.555,36.032 79.407,35.18 79.914,35.18 ; 79.915,35.181 80.279,35.545 80.578,35.545 80.674,35.449 80.929,35.449 81.182,35.196 81.29,35.196 81.367,35.274 81.367,35.691 81.436,35.759 81.654,35.759 U2.C11@81.66,35.765
DDR_DQ9_B: U1.K25 U2.Y11 | length 23.9
  Top Layer w0.09: U1.K25@68.375,43.325 68.625,43.575 68.984,43.575 69.183,43.774 72.374,43.774 72.545,43.945 74.245,43.945 74.323,44.023 74.323,44.15 74.236,44.237 73.921,44.237 73.826,44.333 73.826,45.226 74.697,46.097 75.451,46.097 75.525,46.172 75.525,46.802 75.598,46.874 75.74,46.874 75.816,46.799 75.816,46.203 75.886,46.133 76.522,46.133 76.949,45.706 76.949,45.225 77.018,45.156 77.361,45.156 77.44,45.077 77.44,43.24 77.51,43.17 78.237,43.17 78.31,43.243 78.31,45.1 78.41,45.2 78.537,45.2 78.629,45.108 78.629,44.919 78.706,44.842 78.874,44.842 78.954,44.923 78.954,45.093 79.515,45.654 79.655,45.654 ; 79.656,45.654 79.765,45.763 79.765,45.982 79.769,45.982 80.194,46.407 80.194,46.626 80.403,46.835 80.477,46.835 80.783,47.142 81.038,47.142 81.196,47.3 81.327,47.3 81.447,47.18 81.577,47.18 81.659,47.097 U2.Y11@81.66,46.815
DDR_DQ10_A: U1.P27 U2.E11 | length 20.4
  Top Layer w0.09: U1.P27@69.377,41.329 69.401,41.305 72.532,41.305 73.817,40.02 76.417,40.02 76.525,39.912 76.525,38.936 76.632,38.829 77.276,38.829 77.395,38.948 77.395,39.902 77.513,40.02 78.731,40.02 78.845,39.906 78.845,37.032 79.049,36.828 79.049,36.501 78.845,36.297 78.845,36.152 79.527,35.47 79.795,35.47 80.08,35.755 80.08,36.576 80.171,36.667 80.608,36.667 80.69,36.749 81.006,36.749 81.1,36.655 81.304,36.655 81.66,37.01 U2.E11@81.66,37.065
DDR_DQ10_B: U1.K26 U2.V11 | length 23.8
  Top Layer w0.09: U1.K26@68.875,43.325 68.898,43.35 69.03,43.35 69.257,43.578 72.588,43.578 72.665,43.655 74.226,43.655 74.426,43.456 74.544,43.456 74.613,43.525 74.613,44.465 74.55,44.527 74.217,44.527 74.116,44.629 74.116,45.105 74.809,45.799 75.413,45.799 75.484,45.728 75.484,44.878 75.536,44.825 75.722,44.825 75.775,44.878 75.775,45.768 75.85,45.843 76.402,45.843 76.659,45.586 76.659,44.906 76.729,44.836 77.082,44.836 77.15,44.768 77.15,42.954 77.224,42.88 78.527,42.88 78.6,42.953 78.6,43.859 78.782,44.041 78.782,44.151 78.6,44.333 78.6,44.461 78.691,44.552 78.848,44.552 79.015,44.385 79.126,44.385 79.253,44.512 79.253,44.982 79.635,45.364 79.776,45.364 80.055,45.643 80.055,45.862 80.257,46.064 80.543,46.064 80.798,45.809 81.011,45.809 81.231,46.029 81.379,46.029 81.62,45.788 81.62,45.554 U2.V11@81.66,45.515
DDR_DQ11_A: U1.P26 U2.F11 | length 20.8
  Top Layer w0.09: U1.P26@68.875,41.325 68.889,41.339 69.035,41.339 69.271,41.575 69.638,41.575 69.658,41.555 72.692,41.555 73.937,40.31 76.699,40.31 76.815,40.194 76.815,39.398 76.897,39.316 77.031,39.316 77.105,39.39 77.105,40.203 77.212,40.31 79.002,40.31 79.135,40.177 79.135,37.152 79.342,36.945 79.342,36.066 79.439,35.968 79.583,35.968 79.779,36.165 79.779,36.816 80.002,37.04 80.002,37.417 80.155,37.569 80.502,37.569 80.697,37.374 81.331,37.374 U2.F11@81.666,37.709
DDR_DQ11_B: U1.K27 U2.U11 | length 23.1
  Top Layer w0.09: U1.K27@69.377,43.329 69.388,43.34 72.76,43.34 72.785,43.365 74.106,43.365 74.305,43.166 74.514,43.166 74.604,43.076 74.604,42.916 74.709,42.81 74.817,42.81 74.903,42.896 74.903,44.715 74.801,44.817 74.539,44.817 74.441,44.915 74.441,45.021 74.554,45.134 74.755,45.134 74.835,45.214 74.835,45.415 74.929,45.509 75.106,45.509 75.194,45.421 75.194,44.6 75.259,44.535 75.994,44.535 76.065,44.606 76.065,45.473 76.145,45.553 76.244,45.553 76.369,45.428 76.369,44.616 76.438,44.546 76.788,44.546 76.86,44.474 76.86,42.666 76.937,42.59 78.805,42.59 78.89,42.675 78.89,43.739 79.072,43.921 79.072,44.007 79.16,44.095 79.246,44.095 79.543,44.392 79.543,44.861 79.756,45.074 ; 79.757,45.074 79.896,45.074 80.196,45.374 80.482,45.374 80.636,45.22 81.018,45.22 81.212,45.414 81.35,45.414 81.44,45.324 81.44,45.085 U2.U11@81.66,44.865
DDR_DQ12_A: U1.V26 U2.F9 | length 24
  Top Layer w0.09: U1.V26@68.875,39.325 68.889,39.339 69.035,39.339 69.271,39.575 69.479,39.575 69.525,39.529 71.083,39.529 72.872,37.74 74.033,37.74 78.583,33.19 78.607,33.19 79.737,33.19 79.918,33.01 82.602,33.01 82.782,33.19 83.598,33.19 84.671,34.263 84.671,35.154 84.72,35.203 84.72,36.094 84.451,36.363 84.451,36.43 84.168,36.713 83.209,36.713 82.975,36.947 82.975,37.183 83.112,37.32 83.112,37.567 U2.F9@83.26,37.715
DDR_DQ12_B: U1.L25 U2.U9 | length 24.7
  Top Layer w0.09: U1.L25@68.375,42.825 68.381,42.825 68.647,42.559 73.739,42.559 74.537,41.76 75.661,41.76 75.74,41.839 75.74,43.628 75.817,43.705 75.956,43.705 76.03,43.631 76.03,41.834 76.105,41.76 79.329,41.76 79.441,41.872 79.607,41.872 79.791,41.689 ; 79.792,41.689 80.248,41.689 80.408,41.529 82.109,41.529 82.275,41.695 83.003,41.695 83.277,41.969 84.169,41.969 84.445,42.244 84.517,42.244 84.719,42.446 84.719,42.814 84.355,43.178 84.355,43.916 84.569,44.13 84.569,44.254 84.476,44.347 84.354,44.347 84.352,44.349 84.336,44.349 84.145,44.54 83.927,44.54 83.602,44.865 U2.U9@83.26,44.865
DDR_DQ13_A: U1.V27 U2.E9 | length 23.7
  Top Layer w0.09: U1.V27@69.377,39.329 69.387,39.339 70.863,39.339 72.752,37.45 73.913,37.45 78.462,32.9 78.465,32.9 79.616,32.9 79.737,32.78 ; 79.738,32.78 82.782,32.78 82.902,32.9 83.718,32.9 84.961,34.143 84.961,35.027 85.01,35.075 85.01,36.214 84.839,36.385 84.839,37.024 84.513,37.35 83.545,37.35 U2.E9@83.26,37.065
DDR_DQ13_B: U1.N25 U2.V9 | length 23.2
  Top Layer w0.09: U1.N25@68.377,41.829 68.377,41.891 68.653,42.167 73.311,42.167 74.297,41.18 79.884,41.18 ; 79.886,41.18 79.921,41.144 83.272,41.144 83.517,41.389 84.204,41.389 85.184,42.369 85.184,44.071 85.1,44.155 85.1,44.832 84.977,44.955 84.977,45.126 84.854,45.249 84.854,45.713 84.698,45.869 83.648,45.869 83.273,45.494 U2.V9@83.259,45.494
DDR_DQ14_A: U1.V25 U2.C9 | length 21.7
  Top Layer w0.09: U1.V25@68.374,39.326 68.623,39.575 69.003,39.575 69.193,39.765 69.557,39.765 69.603,39.719 71.303,39.719 72.992,38.03 74.466,38.03 74.535,37.961 74.535,37.648 78.703,33.48 79.858,33.48 80.098,33.24 82.4,33.24 82.63,33.47 83.468,33.47 84.381,34.383 84.381,34.666 84.25,34.797 83.958,34.797 83.775,34.98 83.775,35.413 83.463,35.725 83.3,35.725 U2.C9@83.26,35.765
DDR_DQ14_B: U1.N26 U2.Y9 | length 24
  Top Layer w0.09: U1.N26@68.875,41.825 69.008,41.958 73.109,41.958 74.177,40.89 83.701,40.89 83.91,41.099 84.183,41.099 85.374,42.29 85.374,44.689 85.307,44.756 85.307,45.206 85.144,45.369 85.144,45.833 85.044,45.933 85.044,46.117 84.729,46.432 84.729,46.632 84.725,46.632 84.257,47.1 83.84,47.1 83.554,46.814 U2.Y9@83.26,46.815
DDR_DQ15_A: U1.U25 U2.B9 | length 20.8
  Top Layer w0.09: U1.U25@68.377,39.829 68.625,40.077 68.894,40.077 68.956,40.14 69.692,40.14 69.727,40.104 71.739,40.104 73.233,38.61 74.955,38.61 75.115,38.45 75.115,37.888 76.306,36.697 76.458,36.697 76.816,37.055 77.259,37.055 77.435,36.879 77.435,36.413 77.178,36.156 77.178,35.825 78.943,34.06 80.098,34.06 80.458,33.7 82.011,33.7 82.293,33.982 82.56,33.982 82.687,33.855 83.053,33.855 83.545,34.347 83.545,34.593 83.28,34.858 83.28,35.073 U2.B9@83.259,35.094
DDR_DQ15_B: U1.P25 U2.AA9 | length 25.7
  Top Layer w0.09: U1.P25@68.374,41.326 68.623,41.575 69.003,41.575 69.193,41.765 72.892,41.765 74.057,40.6 83.953,40.6 85.564,42.211 85.564,45.392 85.434,45.522 85.434,46.138 85.019,46.553 85.019,46.752 84.345,47.426 84.345,47.583 84.178,47.75 83.572,47.75 U2.AA9@83.266,47.444
DDR_DQMI0_A: U1.AB25 U2.C3 | length 28.3
  Top Layer w0.09: U1.AB25@68.375,37.325 68.375,37.336 68.614,37.575 68.979,37.575 69.169,37.765 69.722,37.765 70.535,36.952 70.535,36.336 71.1,35.771 71.617,35.771 71.806,35.582 71.806,35.066 72.238,34.633 73.02,33.851 74.022,33.851 74.246,33.627 74.246,32.625 75.961,30.91 84.543,30.91 84.628,30.995 85.037,30.995 85.122,30.91 85.714,30.91 86.19,31.386 86.19,31.567 86.434,31.811 86.615,31.811 87.053,32.249 87.053,32.512 87.295,32.754 87.558,32.754 87.975,33.171 88.159,33.171 88.619,33.632 88.619,34.303 88.559,34.363 88.559,35.266 U2.C3@88.06,35.765
DDR_DQMI0_B: U1.G27 U2.Y3 | length 25.8
  Top Layer w0.09: U1.G27@69.377,44.829 71.378,44.829 74.874,48.324 75.323,48.324 75.41,48.412 75.41,48.838 75.708,49.136 76.043,49.136 76.279,48.9 76.279,48.426 77.807,46.898 78.017,46.898 78.346,47.228 78.721,47.228 79.403,47.911 79.403,48.068 79.693,48.358 ; 79.694,48.358 79.694,48.761 79.398,49.057 79.398,49.19 79.478,49.27 85.368,49.27 ; 85.369,49.27 85.63,49.009 85.981,49.009 86.156,48.834 86.353,48.834 86.764,48.423 86.764,47.889 86.952,47.701 86.952,47.333 87.16,47.126 87.365,47.126 87.587,47.347 87.719,47.347 87.815,47.251 87.815,47.033 88.034,46.815 U2.Y3@88.06,46.815
DDR_DQMI1_A: U1.U26 U2.C10 | length 20.8
  Top Layer w0.09: U1.U26@68.875,39.825 68.91,39.825 69.038,39.953 69.624,39.953 69.663,39.914 71.519,39.914 73.113,38.32 74.586,38.32 74.825,38.081 74.825,37.768 76.209,36.384 76.689,36.384 76.888,36.185 76.888,35.705 78.823,33.77 79.978,33.77 80.278,33.47 82.204,33.47 82.394,33.66 83.161,33.66 83.351,33.85 83.492,33.85 83.735,34.093 83.735,34.722 83.584,34.873 83.584,35.194 83.347,35.431 82.794,35.431 U2.C10@82.46,35.765
DDR_DQMI1_B: U1.M25 U2.Y10 | length 23.7
  Top Layer w0.09: U1.M25@68.375,42.325 68.378,42.328 68.545,42.328 68.571,42.353 73.528,42.353 74.414,41.467 80.047,41.467 80.177,41.336 82.326,41.336 82.392,41.402 83.12,41.402 83.394,41.676 84.218,41.676 84.906,42.364 84.906,44.41 84.824,44.492 84.824,44.837 84.505,45.156 83.205,45.156 82.941,45.42 82.941,46.51 82.778,46.673 82.618,46.673 82.479,46.812 U2.Y10@82.463,46.812
DDR_DQS0_A_N: U1.AA26 U2.E3 | length 30.5
  Top Layer w0.09: U1.AA26@68.875,37.825 68.875,37.832 68.998,37.955 69.843,37.955 70.825,36.973 70.825,36.456 71.22,36.061 71.737,36.061 72.096,35.702 72.096,35.186 72.346,34.935 72.695,34.935 72.863,35.104 72.982,35.104 73.066,35.02 73.066,34.896 72.882,34.712 72.882,34.399 73.14,34.141 74.43,34.141 74.536,34.036 74.536,32.746 76.081,31.2 84.422,31.2 84.764,31.542 84.9,31.542 85.242,31.2 85.594,31.2 85.9,31.506 85.9,31.852 85.613,32.139 85.613,32.242 85.688,32.318 85.933,32.318 86.149,32.101 86.495,32.101 86.763,32.369 86.763,32.785 87.022,33.044 87.438,33.044 87.671,33.277 87.671,34.119 87.764,34.212 87.764,35.978 87.885,36.099 88.181,36.099 88.354,36.272 88.354,36.771 U2.E3@88.06,37.065
DDR_DQS0_A_P: U1.AA25 U2.D3 | length 29.9
  Top Layer w0.09: U1.AA25@68.375,37.825 68.62,38.07 68.76,38.07 68.894,38.205 69.947,38.205 71.075,37.077 71.075,36.56 71.324,36.311 71.841,36.311 72.346,35.806 72.346,35.289 72.449,35.185 72.591,35.185 72.76,35.354 73.086,35.354 73.316,35.124 73.316,34.792 73.132,34.608 73.132,34.503 73.243,34.391 74.534,34.391 74.786,34.139 74.786,32.849 76.185,31.45 84.319,31.45 84.66,31.792 85.004,31.792 85.345,31.45 85.49,31.45 85.65,31.609 85.65,31.748 85.363,32.035 85.363,32.346 85.584,32.568 86.037,32.568 86.253,32.351 86.392,32.351 86.513,32.473 86.513,32.888 86.919,33.294 87.334,33.294 87.421,33.381 87.421,34.223 87.554,34.356 87.554,36.145 87.758,36.349 87.937,36.349 88.003,36.415 U2.D3@88.06,36.415
DDR_DQS0_B_N: U1.F26 U2.V3 | length 29.3
  Top Layer w0.09: U1.F26@68.877,45.329 68.904,45.356 69.05,45.356 69.273,45.579 70.955,45.579 75.475,50.1 76.893,50.1 77.109,49.883 77.109,48.77 77.278,48.602 77.383,48.602 77.477,48.696 77.477,48.829 77.692,49.044 78.052,49.044 78.269,48.827 78.269,48.469 78.34,48.398 78.492,48.398 78.559,48.465 78.559,49.937 78.722,50.1 86.587,50.1 86.816,49.872 86.816,49.404 87.299,48.92 88.022,48.92 88.564,48.378 88.564,46.284 88.414,46.134 88.414,45.997 88.093,45.676 88.093,45.528 U2.V3@88.059,45.494
DDR_DQS0_B_P: U1.F27 U2.W3 | length 27.5
  Top Layer w0.09: U1.F27@69.377,45.329 71.058,45.329 75.579,49.85 76.789,49.85 ; 76.795,49.843 76.859,49.78 76.859,48.667 77.174,48.352 77.487,48.352 77.727,48.592 77.727,48.726 77.795,48.794 77.949,48.794 78.019,48.724 78.019,48.366 78.236,48.148 78.595,48.148 78.809,48.362 78.809,49.777 78.882,49.85 86.484,49.85 86.566,49.768 86.566,49.3 87.196,48.67 87.918,48.67 88.354,48.234 88.354,46.427 88.071,46.144 U2.W3@88.059,46.144
DDR_DQS1_A_N: U1.R25 U2.E10 | length 20.8
  Top Layer w0.09: U1.R25@68.375,40.825 68.392,40.825 68.584,40.633 68.713,40.633 68.771,40.575 72.031,40.575 73.456,39.15 75.427,39.15 75.655,38.922 75.655,38.127 76.271,37.511 76.377,37.511 76.638,37.772 77.306,37.772 77.975,37.103 77.975,35.792 79.167,34.6 80.32,34.6 ; 80.321,34.601 80.742,34.18 81.812,34.18 81.954,34.322 81.954,36.243 82.104,36.393 82.104,36.709 U2.E10@82.46,37.065
DDR_DQS1_A_P: U1.T25 U2.D10 | length 20.4
  Top Layer w0.09: U1.T25@68.375,40.325 68.413,40.325 68.471,40.383 68.61,40.383 68.668,40.325 71.928,40.325 73.28,38.973 73.353,38.9 75.323,38.9 75.405,38.818 75.405,38.024 76.168,37.261 76.481,37.261 76.742,37.522 77.202,37.522 77.725,36.999 77.725,35.689 79.063,34.35 80.217,34.35 ; 80.218,34.351 80.638,33.93 81.916,33.93 82.164,34.178 82.164,36.099 U2.D10@82.459,36.394
DDR_DQS1_B_N: U1.L27 U2.V10 | length 24.1
  Top Layer w0.09: U1.L27@69.377,42.825 73.816,42.825 ; 73.827,42.825 73.883,42.825 74.658,42.05 75.208,42.05 75.443,42.285 75.443,43.927 75.511,43.995 76.251,43.995 76.32,43.926 76.32,42.298 76.569,42.05 79.156,42.05 79.43,42.324 79.43,43.515 79.765,43.85 ; 79.766,43.85 79.912,43.85 80.167,43.596 80.167,43.491 79.764,43.088 79.764,42.127 79.984,41.907 80.447,41.907 80.633,41.72 81.89,41.72 82.164,41.994 82.164,45.219 U2.V10@82.46,45.515
DDR_DQS1_B_P: U1.L26 U2.W10 | length 25.1
  Top Layer w0.09: U1.L26@68.877,42.829 68.879,42.829 69.125,43.075 73.986,43.075 74.761,42.3 75.105,42.3 75.193,42.388 75.193,44.031 75.407,44.245 76.355,44.245 76.57,44.03 76.57,42.402 76.672,42.3 79.052,42.3 79.18,42.427 79.18,43.618 79.662,44.1 ; 79.663,44.1 80.016,44.1 80.417,43.699 80.417,43.387 80.014,42.984 80.014,42.23 80.088,42.157 80.55,42.157 80.737,41.97 81.786,41.97 81.954,42.138 81.954,45.427 82.464,45.937 82.464,46.161 U2.W10@82.46,46.165
DDR_RESETN: R42.2 U1.E21 U2.T11 | length 18.5
  Top Layer w0.09: v2(66.35,45.375) 66.369,45.394 U1.E21@66.369,45.819 ; v4@79.881,44.707 79.994,44.707 80.065,44.636 80.492,44.636 80.562,44.565 81.31,44.565 U2.T11@81.66,44.215
  Bottom Layer w0.09: v2@66.35,45.35 v2@66.35,45.434 ; v2@66.351,45.429 66.53,45.608 66.53,45.984 66.732,46.186 66.738,46.186 68.347,47.795 73.474,47.795 76.199,45.069 79.066,45.069 79.415,44.719 v4@79.895,44.719
  other v4: 79.895,44.725
eMMC.SDMMC2_CK: R103.1 U1.B25 U37.M6 | length 19.1
  Top Layer w0.09: U1.B25@68.375,47.325 68.402,47.352 68.402,48.575 ; 79.175,55.037 79.175,55.273 ; 79.175,55.537 79.175,55.773 ; 79.175,56.037 79.175,56.273
  Top Layer w0.11: 68.402,48.575 68.402,49.127 69.459,50.184 69.734,50.184 73.725,54.175 75.95,54.175 76.481,54.706 79.022,54.706 79.175,54.858 79.175,55.037 ; 79.175,55.273 79.175,55.405 ; 79.175,55.407 79.175,55.537 ; 79.175,55.773 79.175,55.905 ; 79.175,55.907 79.175,56.037 ; 79.175,56.273 79.175,56.372 79.095,56.452 79.095,56.87 79.281,57.056 v2(79.425,57.375) 79.705,57.655 U37.M6@79.925,57.655
  Bottom Layer w0.11: v2(79.425,57.375) 79.762,57.375 80.076,57.061 R103.1@80.171,57.061
eMMC.SDMMC2_CMD: R104.1 U1.D24 U37.M5 | length 20
  Top Layer w0.09: U1.D24@67.875,46.325 68.125,46.575 68.479,46.575 68.625,46.721 68.625,47.429 68.615,47.439 68.615,47.453 ; 79.675,55.037 79.675,55.273 ; 79.675,55.537 79.675,55.773 ; 79.675,56.037 79.675,56.273
  Top Layer w0.11: 68.616,47.451 68.615,47.453 68.615,47.933 68.625,47.943 68.625,48.699 69.588,49.662 69.816,49.662 74.029,53.875 76.15,53.875 76.674,54.399 79.162,54.399 79.675,54.911 79.675,55.037 ; 79.675,55.273 79.675,55.405 ; 79.675,55.407 79.675,55.537 ; 79.675,55.773 79.675,55.905 ; 79.675,55.907 79.675,56.037 ; 79.675,56.273 79.675,56.46 v2(79.45,56.685) U37.M5@79.92,57.155
  Bottom Layer w0.11: v2(79.45,56.685) 79.724,56.411 80.019,56.411 R104.1@80.175,56.255
eMMC.SDMMC2_D0: R101.1 U1.C24 U37.A3 | length 16
  Top Layer w0.09: U1.C24@67.875,46.825 67.88,46.83 67.88,47.467 67.985,47.572 67.985,48.335 67.902,48.418 67.902,48.575
  Top Layer w0.11: 67.902,48.575 67.902,49.85 71.229,53.177 71.487,53.435 71.597,53.435 71.743,53.289 71.852,53.289 71.962,53.399 71.962,53.508 71.778,53.692 71.778,53.801 71.888,53.911 71.998,53.911 72.181,53.727 72.291,53.727 72.4,53.837 72.4,53.947 72.217,54.13 72.217,54.24 72.326,54.349 72.436,54.349 72.62,54.166 72.729,54.166 72.839,54.275 72.839,54.385 72.655,54.569 72.655,54.678 72.765,54.788 72.874,54.788 73.058,54.604 73.168,54.604 73.277,54.714 73.277,54.823 73.131,54.969 73.131,55.079 73.279,55.227 v1(73.884,55.227) 73.884,55.909 74.13,56.155 U37.A3@74.425,56.155
  Bottom Layer w0.11: v1(73.884,55.227) 73.884,55.34 74.056,55.512 74.056,55.556 74.08,55.58 74.08,55.675 74.28,55.875 R101.1@74.375,55.875
eMMC.SDMMC2_D1: U1.B23 U37.A4 | length 18.8
  Top Layer w0.09: U1.B23@67.375,47.325 67.375,47.357 67.52,47.502 67.52,47.616 67.625,47.721 67.625,47.952 67.479,48.098 67.479,48.575
  Top Layer w0.11: 67.479,48.575 67.479,50.504 67.856,50.881 67.895,50.92 67.895,51.03 67.824,51.101 67.824,51.21 67.934,51.32 68.044,51.32 68.165,51.199 68.274,51.199 68.384,51.308 68.384,51.418 68.263,51.539 68.263,51.649 68.372,51.758 68.482,51.758 68.603,51.637 68.713,51.637 68.822,51.747 68.822,51.856 68.701,51.977 68.701,52.087 68.811,52.197 68.92,52.197 69.042,52.075 69.151,52.075 69.261,52.185 69.261,52.295 69.14,52.416 69.14,52.525 69.249,52.635 69.359,52.635 69.48,52.514 69.59,52.514 69.699,52.623 69.699,52.733 69.578,52.854 69.578,52.964 69.688,53.073 69.797,53.073 69.918,52.952 70.028,52.952 70.138,53.062 70.138,53.171 70.016,53.293 70.016,53.402 70.126,53.512 70.236,53.512 70.357,53.391 70.466,53.391 70.576,53.5 70.576,53.61 70.455,53.731 70.455,53.841 70.564,53.95 70.674,53.95 70.795,53.829 70.905,53.829 71.014,53.939 71.014,54.048 70.893,54.169 70.893,54.279 71.003,54.389 71.112,54.389 71.234,54.267 71.343,54.267 71.453,54.377 71.453,54.487 71.332,54.608 71.332,54.718 71.441,54.827 71.551,54.827 71.672,54.706 71.782,54.706 71.891,54.815 71.891,54.925 71.77,55.046 71.77,55.156 71.88,55.266 71.989,55.266 72.11,55.144 72.22,55.144 72.33,55.254 72.33,55.363 72.208,55.485 72.208,55.594 72.318,55.704 72.428,55.704 72.549,55.583 72.658,55.583 72.768,55.692 72.768,55.802 72.647,55.923 72.647,56.033 72.756,56.142 72.866,56.142 72.987,56.021 73.097,56.021 73.206,56.131 73.206,56.24 73.085,56.362 73.085,56.471 73.195,56.581 73.304,56.581 73.375,56.51 73.485,56.51 73.536,56.561 73.63,56.655 U37.A4@74.425,56.655
eMMC.SDMMC2_D2: U1.C23 U37.A5 | length 14.7
  Top Layer w0.09: 67.055,48.395 67.055,47.999 67.125,47.929 67.125,47.075 U1.C23@67.375,46.825
  Top Layer w0.11: 67.054,48.395 67.057,48.398 67.057,51.657 72.691,57.291 72.984,57.291 73.12,57.155 74.056,57.155 U37.A5@74.425,57.155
